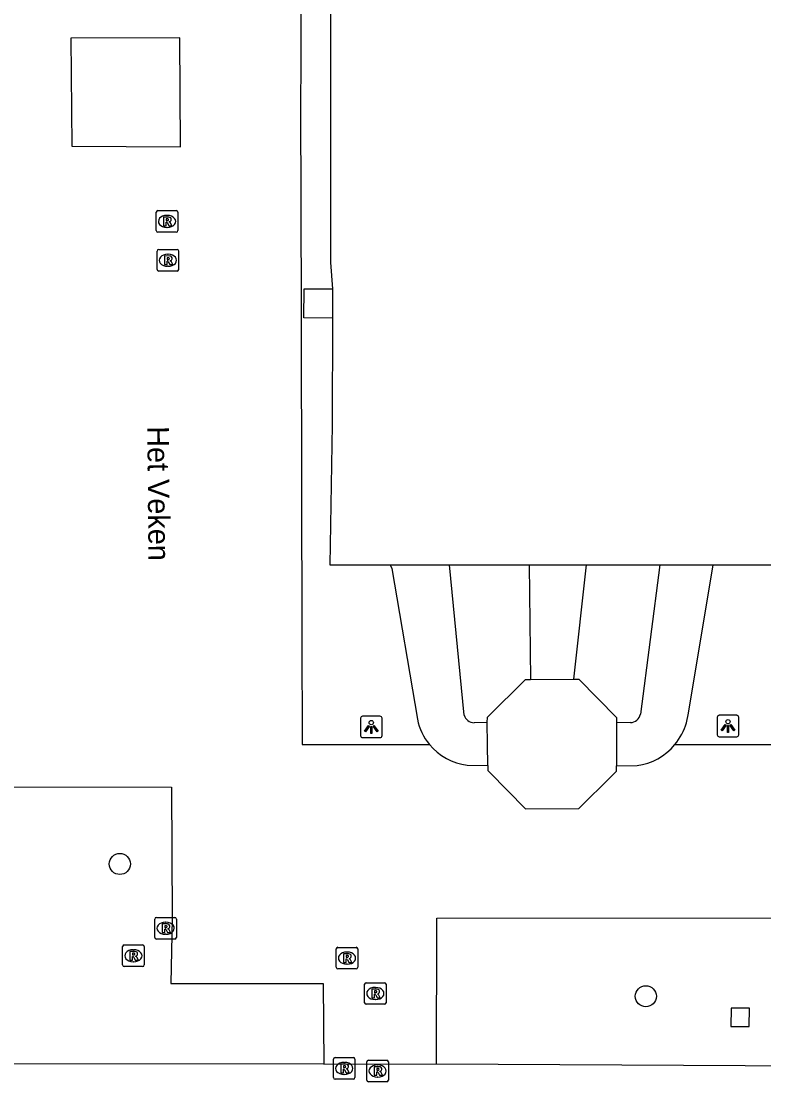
# Model space of a CAD drawing. Extents: x 161477 to 163040, y 383680 to 384868.
# Drawn here: x 162022.66 to 162057.1, y 384190.13 to 384239.31 of the extents above; entities that cross this region are included whole.
import ezdxf

# ---------------------------------------------------------------- set-up
doc = ezdxf.new("R2010")
doc.units = 0
for name, color, linetype in [('IMGEO_Boom', 7, 'Continuous'), ('IMGEO_Groenvoorziening', 7, 'Continuous'), ('IMGEO_Lichtpunt', 7, 'Continuous'), ('IMGEO_Openbare_ruimte_label', 7, 'Continuous'), ('IMGEO_Pand', 7, 'Continuous'), ('IMGEO_Rioolput', 7, 'Continuous'), ('IMGEO_Voetpad_gesloten', 7, 'Continuous'), ('IMGEO_Voetpad_open', 7, 'Continuous')]:
    doc.layers.add(name, color=color, linetype=linetype)

msp = doc.modelspace()

# ---------------------------------------------------------------- linework, layer by layer
at = {"layer": 'IMGEO_Boom'}
for centre in [(162027.23, 384200.233), (162051.624, 384194.101)]:
    msp.add_circle(centre, 0.489, dxfattribs=at)
at = {"layer": 'IMGEO_Groenvoorziening'}
for points in [[(162039.764, 384214.102), (162039.843, 384213.943), (162041.029, 384206.942)], [(162043.196, 384207.129), (162042.524, 384214.109)], [(162046.212, 384214.11), (162046.269, 384208.792)], [(162048.861, 384214.111), (162048.271, 384208.804)], [(162052.282, 384214.112), (162051.378, 384207.188)], [(162053.515, 384206.785), (162053.604, 384207.234), (162054.752, 384214.113)], [(162044.274, 384206.789), (162043.657, 384206.781)], [(162050.909, 384206.788), (162050.259, 384206.785)]]:
    msp.add_lwpolyline(points, dxfattribs=at)
for centre, radius, start, end in [((162043.669, 384207.49), 2.696, 191.7325, 219.4536), ((162043.678, 384207.288), 0.507, 198.2253, 267.6778), ((162050.877, 384207.3), 0.513, 273.5225, 347.3978), ((162050.885, 384207.55), 2.738, 319.4429, 343.7876)]:
    msp.add_arc(centre, radius, start, end, dxfattribs=at)
at = {"layer": 'IMGEO_Lichtpunt'}
for p, q in [((162038.393, 384206.993), (162038.393, 384206.186)), ((162038.393, 384206.993), (162038.393, 384206.186)), ((162039.295, 384207.088), (162038.487, 384207.088)), ((162039.295, 384207.088), (162038.487, 384207.088)), ((162039.389, 384206.186), (162039.389, 384206.993)), ((162039.389, 384206.186), (162039.389, 384206.993)), ((162054.938, 384207.032), (162054.938, 384206.225)), ((162054.938, 384207.032), (162054.938, 384206.225)), ((162055.84, 384207.127), (162055.032, 384207.127)), ((162055.84, 384207.127), (162055.032, 384207.127)), ((162055.934, 384206.225), (162055.934, 384207.032)), ((162055.934, 384206.225), (162055.934, 384207.032)), ((162038.487, 384206.092), (162039.295, 384206.092)), ((162038.487, 384206.092), (162039.295, 384206.092)), ((162055.032, 384206.131), (162055.84, 384206.131)), ((162055.032, 384206.131), (162055.84, 384206.131))]:
    msp.add_line(p, q, dxfattribs=at)
for points in [[(162038.767, 384206.657), (162038.806, 384206.629), (162038.618, 384206.367), (162038.58, 384206.394), (162038.767, 384206.657)], [(162038.869, 384206.609), (162038.916, 384206.609), (162038.916, 384206.287), (162038.869, 384206.287), (162038.869, 384206.609)], [(162038.979, 384206.629), (162039.017, 384206.656), (162039.204, 384206.394), (162039.165, 384206.366), (162038.979, 384206.629)], [(162055.312, 384206.696), (162055.351, 384206.668), (162055.163, 384206.406), (162055.125, 384206.433), (162055.312, 384206.696)], [(162055.414, 384206.648), (162055.461, 384206.648), (162055.461, 384206.326), (162055.414, 384206.326), (162055.414, 384206.648)], [(162055.524, 384206.668), (162055.562, 384206.695), (162055.749, 384206.433), (162055.71, 384206.405), (162055.524, 384206.668)]]:
    msp.add_lwpolyline(points, dxfattribs=at)
for centre in [(162038.892, 384206.791), (162055.437, 384206.83)]:
    msp.add_circle(centre, 0.0994, dxfattribs=at)
for centre, start, end in [((162038.487, 384206.993), 90, 180), ((162038.487, 384206.993), 90, 180), ((162039.295, 384206.993), 0, 90), ((162039.295, 384206.993), 0, 90), ((162055.032, 384207.032), 90, 180), ((162055.032, 384207.032), 90, 180), ((162055.84, 384207.032), 0, 90), ((162055.84, 384207.032), 0, 90), ((162038.487, 384206.186), 180, 270), ((162038.487, 384206.186), 180, 270), ((162039.295, 384206.186), 270, 0), ((162039.295, 384206.186), 270, 360), ((162055.032, 384206.225), 180, 270), ((162055.032, 384206.225), 180, 270), ((162055.84, 384206.225), 270, 0), ((162055.84, 384206.225), 270, 360)]:
    msp.add_arc(centre, 0.0946, start, end, dxfattribs=at)
at = {"layer": 'IMGEO_Pand'}
for points in [[(162082.399, 384225.651), (162082.408, 384231.898), (162082.412, 384234.268), (162082.422, 384240.901), (162061.823, 384240.891), (162060.867, 384240.892), (162058.494, 384240.893), (162057.612, 384240.894), (162036.997, 384240.896), (162036.996, 384234.345), (162036.996, 384231.857), (162036.996, 384231.817), (162036.996, 384228.133), (162037.096, 384226.903)], [(162037.096, 384226.903), (162037.088, 384225.547)], [(162037.088, 384225.547), (162037.077, 384220.594), (162036.972, 384214.106), (162039.764, 384214.102)], [(162054.752, 384214.113), (162082.389, 384214.105), (162082.384, 384220.627), (162082.385, 384220.86)], [(162039.764, 384214.102), (162042.524, 384214.109)], [(162042.524, 384214.109), (162046.212, 384214.11)], [(162046.212, 384214.11), (162048.861, 384214.111)], [(162048.861, 384214.111), (162052.282, 384214.112)], [(162052.282, 384214.112), (162054.752, 384214.113)], [(162044.274, 384206.789), (162044.281, 384207.048), (162046.041, 384208.79), (162046.269, 384208.792)], [(162046.269, 384208.792), (162048.271, 384208.804)], [(162048.271, 384208.804), (162048.518, 384208.804), (162050.258, 384207.019), (162050.259, 384206.785)], [(162044.299, 384204.794), (162044.287, 384205.769), (162044.274, 384206.789)], [(162050.259, 384206.785), (162050.262, 384205.769), (162050.265, 384204.78)], [(162044.299, 384204.794), (162044.302, 384204.562), (162044.371, 384204.491), (162046.038, 384202.787), (162048.513, 384202.804), (162050.048, 384204.318), (162050.266, 384204.533), (162050.265, 384204.78)]]:
    msp.add_lwpolyline(points, dxfattribs=at)
at = {"layer": 'IMGEO_Rioolput'}
for p, q in [((162028.918, 384229.606), (162028.918, 384230.458)), ((162028.993, 384230.532), (162029.845, 384230.532)), ((162029.919, 384230.458), (162029.919, 384229.606)), ((162029.406, 384230.312), (162029.431, 384230.312)), ((162029.845, 384229.532), (162028.993, 384229.532)), ((162029.429, 384229.752), (162029.404, 384229.752)), ((162028.957, 384227.802), (162028.957, 384228.654)), ((162029.032, 384228.728), (162029.884, 384228.728)), ((162029.445, 384228.508), (162029.47, 384228.508)), ((162029.958, 384228.654), (162029.958, 384227.802)), ((162029.468, 384227.948), (162029.443, 384227.948)), ((162029.884, 384227.728), (162029.032, 384227.728)), ((162028.853, 384196.827), (162028.853, 384197.679)), ((162028.928, 384197.753), (162029.78, 384197.753)), ((162029.341, 384197.533), (162029.366, 384197.533)), ((162029.854, 384197.679), (162029.854, 384196.827)), ((162029.364, 384196.973), (162029.339, 384196.973)), ((162027.433, 384196.479), (162028.285, 384196.479)), ((162029.78, 384196.753), (162028.928, 384196.753)), ((162027.358, 384195.553), (162027.358, 384196.405)), ((162027.846, 384196.259), (162027.871, 384196.259)), ((162028.359, 384196.405), (162028.359, 384195.553)), ((162037.264, 384195.442), (162037.264, 384196.294)), ((162037.339, 384196.368), (162038.191, 384196.368)), ((162037.752, 384196.148), (162037.777, 384196.148)), ((162038.265, 384196.294), (162038.265, 384195.442)), ((162027.869, 384195.699), (162027.844, 384195.699)), ((162037.775, 384195.588), (162037.75, 384195.588)), ((162028.285, 384195.479), (162027.433, 384195.479)), ((162038.191, 384195.368), (162037.339, 384195.368)), ((162038.579, 384193.802), (162038.579, 384194.654)), ((162038.654, 384194.728), (162039.506, 384194.728)), ((162039.067, 384194.508), (162039.092, 384194.508)), ((162039.58, 384194.654), (162039.58, 384193.802)), ((162039.506, 384193.728), (162038.654, 384193.728)), ((162039.09, 384193.948), (162039.065, 384193.948)), ((162037.135, 384190.329), (162037.135, 384191.181)), ((162037.21, 384191.255), (162038.062, 384191.255)), ((162038.136, 384191.181), (162038.136, 384190.329)), ((162038.685, 384190.208), (162038.685, 384191.06)), ((162038.76, 384191.134), (162039.612, 384191.134)), ((162039.686, 384191.06), (162039.686, 384190.208)), ((162037.623, 384191.035), (162037.648, 384191.035)), ((162039.173, 384190.914), (162039.198, 384190.914)), ((162038.062, 384190.255), (162037.21, 384190.255)), ((162037.646, 384190.475), (162037.621, 384190.475)), ((162039.612, 384190.134), (162038.76, 384190.134)), ((162039.196, 384190.354), (162039.171, 384190.354))]:
    msp.add_line(p, q, dxfattribs=at)
for points in [[(162028.918, 384229.606), (162028.918, 384230.458)], [(162028.993, 384230.532), (162029.845, 384230.532)], [(162029.919, 384230.458), (162029.919, 384229.606)], [(162029.507, 384230.23), (162029.255, 384230.232), (162029.255, 384229.832)], [(162029.255, 384229.832), (162029.379, 384229.832), (162029.379, 384229.994), (162029.39, 384229.994)], [(162029.433, 384230.151), (162029.379, 384230.151), (162029.379, 384230.07)], [(162029.379, 384230.07), (162029.431, 384230.07)], [(162029.437, 384229.965), (162029.508, 384229.832), (162029.648, 384229.832), (162029.583, 384229.958)], [(162029.845, 384229.532), (162028.993, 384229.532)], [(162028.957, 384227.802), (162028.957, 384228.654)], [(162029.032, 384228.728), (162029.884, 384228.728)], [(162029.958, 384228.654), (162029.958, 384227.802)], [(162029.546, 384228.426), (162029.294, 384228.428), (162029.294, 384228.028)], [(162029.294, 384228.028), (162029.418, 384228.028), (162029.418, 384228.19), (162029.429, 384228.19)], [(162029.472, 384228.347), (162029.418, 384228.347), (162029.418, 384228.266)], [(162029.418, 384228.266), (162029.47, 384228.266)], [(162029.476, 384228.161), (162029.547, 384228.028), (162029.687, 384228.028), (162029.622, 384228.154)], [(162029.884, 384227.728), (162029.032, 384227.728)], [(162028.853, 384196.827), (162028.853, 384197.679)], [(162028.928, 384197.753), (162029.78, 384197.753)], [(162029.442, 384197.451), (162029.19, 384197.453), (162029.19, 384197.053)], [(162029.854, 384197.679), (162029.854, 384196.827)], [(162029.19, 384197.053), (162029.314, 384197.053), (162029.314, 384197.215), (162029.325, 384197.215)], [(162029.368, 384197.372), (162029.314, 384197.372), (162029.314, 384197.291)], [(162029.314, 384197.291), (162029.366, 384197.291)], [(162029.372, 384197.186), (162029.443, 384197.053), (162029.583, 384197.053), (162029.518, 384197.179)], [(162027.433, 384196.479), (162028.285, 384196.479)], [(162029.78, 384196.753), (162028.928, 384196.753)], [(162027.358, 384195.553), (162027.358, 384196.405)], [(162027.947, 384196.177), (162027.695, 384196.179), (162027.695, 384195.779)], [(162027.873, 384196.098), (162027.819, 384196.098), (162027.819, 384196.017)], [(162027.819, 384196.017), (162027.871, 384196.017)], [(162028.359, 384196.405), (162028.359, 384195.553)], [(162037.264, 384195.442), (162037.264, 384196.294)], [(162037.339, 384196.368), (162038.191, 384196.368)], [(162037.853, 384196.066), (162037.601, 384196.068), (162037.601, 384195.668)], [(162037.779, 384195.987), (162037.725, 384195.987), (162037.725, 384195.906)], [(162038.265, 384196.294), (162038.265, 384195.442)], [(162027.695, 384195.779), (162027.819, 384195.779), (162027.819, 384195.941), (162027.83, 384195.941)], [(162027.877, 384195.912), (162027.948, 384195.779), (162028.088, 384195.779), (162028.023, 384195.905)], [(162037.601, 384195.668), (162037.725, 384195.668), (162037.725, 384195.83), (162037.736, 384195.83)], [(162037.725, 384195.906), (162037.777, 384195.906)], [(162037.783, 384195.801), (162037.854, 384195.668), (162037.994, 384195.668), (162037.929, 384195.794)], [(162028.285, 384195.479), (162027.433, 384195.479)], [(162038.191, 384195.368), (162037.339, 384195.368)], [(162038.579, 384193.802), (162038.579, 384194.654)], [(162038.654, 384194.728), (162039.506, 384194.728)], [(162039.58, 384194.654), (162039.58, 384193.802)], [(162039.168, 384194.426), (162038.916, 384194.428), (162038.916, 384194.028)], [(162038.916, 384194.028), (162039.04, 384194.028), (162039.04, 384194.19), (162039.051, 384194.19)], [(162039.094, 384194.347), (162039.04, 384194.347), (162039.04, 384194.266)], [(162039.04, 384194.266), (162039.092, 384194.266)], [(162039.098, 384194.161), (162039.169, 384194.028), (162039.309, 384194.028), (162039.244, 384194.154)], [(162039.506, 384193.728), (162038.654, 384193.728)], [(162037.135, 384190.329), (162037.135, 384191.181)], [(162037.21, 384191.255), (162038.062, 384191.255)], [(162038.136, 384191.181), (162038.136, 384190.329)], [(162038.685, 384190.208), (162038.685, 384191.06)], [(162038.76, 384191.134), (162039.612, 384191.134)], [(162039.686, 384191.06), (162039.686, 384190.208)], [(162037.724, 384190.953), (162037.472, 384190.955), (162037.472, 384190.555)], [(162037.472, 384190.555), (162037.596, 384190.555), (162037.596, 384190.717), (162037.607, 384190.717)], [(162037.65, 384190.874), (162037.596, 384190.874), (162037.596, 384190.793)], [(162037.596, 384190.793), (162037.648, 384190.793)], [(162037.654, 384190.688), (162037.725, 384190.555), (162037.865, 384190.555), (162037.8, 384190.681)], [(162039.274, 384190.832), (162039.022, 384190.834), (162039.022, 384190.434)], [(162039.022, 384190.434), (162039.146, 384190.434), (162039.146, 384190.596), (162039.157, 384190.596)], [(162039.2, 384190.753), (162039.146, 384190.753), (162039.146, 384190.672)], [(162039.146, 384190.672), (162039.198, 384190.672)], [(162039.204, 384190.567), (162039.275, 384190.434), (162039.415, 384190.434), (162039.35, 384190.56)], [(162038.062, 384190.255), (162037.21, 384190.255)], [(162039.612, 384190.134), (162038.76, 384190.134)]]:
    msp.add_lwpolyline(points, dxfattribs=at)
for centre, radius, start, end in [((162028.995, 384230.456), 0.0765, 91.552, 178.448), ((162028.995, 384230.456), 0.0765, 91.552, 178.448), ((162029.843, 384230.456), 0.0765, 1.552, 88.448), ((162029.843, 384230.456), 0.0765, 1.552, 88.448), ((162029.389, 384229.941), 0.0533, 26.0293, 88.6989), ((162029.415, 384230.259), 0.19, 274.7715, 282.9687), ((162029.439, 384230.055), 0.0964, 77.0061, 93.1865), ((162029.453, 384230.112), 0.0378, 276.6634, 79.6772), ((162029.506, 384230.12), 0.109, 350.3612, 89.416), ((162029.504, 384230.12), 0.112, 277.5842, 350.9817), ((162029.488, 384229.905), 0.108, 29.5134, 73.7905), ((162028.995, 384229.608), 0.0765, 181.552, 268.448), ((162028.995, 384229.608), 0.0765, 181.552, 268.448), ((162029.843, 384229.608), 0.0765, 271.552, 358.448), ((162029.843, 384229.608), 0.0765, 271.552, 358.448), ((162029.034, 384228.652), 0.0765, 91.552, 178.448), ((162029.034, 384228.652), 0.0765, 91.552, 178.448), ((162029.882, 384228.652), 0.0765, 1.552, 88.448), ((162029.882, 384228.652), 0.0765, 1.552, 88.448), ((162029.428, 384228.137), 0.0533, 26.0293, 88.6989), ((162029.454, 384228.455), 0.19, 274.7715, 282.9687), ((162029.478, 384228.251), 0.0964, 77.0061, 93.1865), ((162029.492, 384228.308), 0.0378, 276.6634, 79.6772), ((162029.545, 384228.316), 0.109, 350.3612, 89.416), ((162029.543, 384228.316), 0.112, 277.5842, 350.9817), ((162029.527, 384228.101), 0.108, 29.5134, 73.7905), ((162029.034, 384227.804), 0.0765, 181.552, 268.448), ((162029.034, 384227.804), 0.0765, 181.552, 268.448), ((162029.882, 384227.804), 0.0765, 271.552, 358.448), ((162029.882, 384227.804), 0.0765, 271.552, 358.448), ((162028.93, 384197.677), 0.0765, 91.552, 178.448), ((162028.93, 384197.677), 0.0765, 91.552, 178.448), ((162029.441, 384197.341), 0.109, 350.3612, 89.416), ((162029.778, 384197.677), 0.0765, 1.552, 88.448), ((162029.778, 384197.677), 0.0765, 1.552, 88.448), ((162029.324, 384197.162), 0.0533, 26.0293, 88.6989), ((162029.35, 384197.48), 0.19, 274.7715, 282.9687), ((162029.374, 384197.276), 0.0964, 77.0061, 93.1865), ((162029.388, 384197.333), 0.0378, 276.6634, 79.6772), ((162029.439, 384197.341), 0.112, 277.5842, 350.9817), ((162029.423, 384197.126), 0.108, 29.5134, 73.7905), ((162027.435, 384196.403), 0.0765, 91.552, 178.448), ((162027.435, 384196.403), 0.0765, 91.552, 178.448), ((162028.283, 384196.403), 0.0765, 1.552, 88.448), ((162028.283, 384196.403), 0.0765, 1.552, 88.448), ((162028.93, 384196.829), 0.0765, 181.552, 268.448), ((162028.93, 384196.829), 0.0765, 181.552, 268.448), ((162029.778, 384196.829), 0.0765, 271.552, 358.448), ((162029.778, 384196.829), 0.0765, 271.552, 358.448), ((162027.855, 384196.206), 0.19, 274.7715, 282.9687), ((162027.879, 384196.002), 0.0964, 77.0061, 93.1865), ((162027.893, 384196.059), 0.0378, 276.6634, 79.6772), ((162027.946, 384196.067), 0.109, 350.3612, 89.416), ((162027.944, 384196.067), 0.112, 277.5842, 350.9817), ((162037.341, 384196.292), 0.0765, 91.552, 178.448), ((162037.341, 384196.292), 0.0765, 91.552, 178.448), ((162037.785, 384195.891), 0.0964, 77.0061, 93.1865), ((162037.799, 384195.948), 0.0378, 276.6634, 79.6772), ((162037.852, 384195.956), 0.109, 350.3612, 89.416), ((162038.189, 384196.292), 0.0765, 1.552, 88.448), ((162038.189, 384196.292), 0.0765, 1.552, 88.448), ((162027.435, 384195.555), 0.0765, 181.552, 268.448), ((162027.435, 384195.555), 0.0765, 181.552, 268.448), ((162027.829, 384195.888), 0.0533, 26.0293, 88.6989), ((162027.928, 384195.852), 0.108, 29.5134, 73.7905), ((162028.283, 384195.555), 0.0765, 271.552, 358.448), ((162028.283, 384195.555), 0.0765, 271.552, 358.448), ((162037.735, 384195.777), 0.0533, 26.0293, 88.6989), ((162037.761, 384196.095), 0.19, 274.7715, 282.9687), ((162037.85, 384195.956), 0.112, 277.5842, 350.9817), ((162037.834, 384195.741), 0.108, 29.5134, 73.7905), ((162037.341, 384195.444), 0.0765, 181.552, 268.448), ((162037.341, 384195.444), 0.0765, 181.552, 268.448), ((162038.189, 384195.444), 0.0765, 271.552, 358.448), ((162038.189, 384195.444), 0.0765, 271.552, 358.448), ((162038.656, 384194.652), 0.0765, 91.552, 178.448), ((162038.656, 384194.652), 0.0765, 91.552, 178.448), ((162039.504, 384194.652), 0.0765, 1.552, 88.448), ((162039.504, 384194.652), 0.0765, 1.552, 88.448), ((162039.05, 384194.137), 0.0533, 26.0293, 88.6989), ((162039.076, 384194.455), 0.19, 274.7715, 282.9687), ((162039.1, 384194.251), 0.0964, 77.0061, 93.1865), ((162039.114, 384194.308), 0.0378, 276.6634, 79.6772), ((162039.167, 384194.316), 0.109, 350.3612, 89.416), ((162039.165, 384194.316), 0.112, 277.5842, 350.9817), ((162039.149, 384194.101), 0.108, 29.5134, 73.7905), ((162038.656, 384193.804), 0.0765, 181.552, 268.448), ((162038.656, 384193.804), 0.0765, 181.552, 268.448), ((162039.504, 384193.804), 0.0765, 271.552, 358.448), ((162039.504, 384193.804), 0.0765, 271.552, 358.448), ((162037.212, 384191.179), 0.0765, 91.552, 178.448), ((162037.212, 384191.179), 0.0765, 91.552, 178.448), ((162038.06, 384191.179), 0.0765, 1.552, 88.448), ((162038.06, 384191.179), 0.0765, 1.552, 88.448), ((162038.762, 384191.058), 0.0765, 91.552, 178.448), ((162038.762, 384191.058), 0.0765, 91.552, 178.448), ((162039.61, 384191.058), 0.0765, 1.552, 88.448), ((162039.61, 384191.058), 0.0765, 1.552, 88.448), ((162037.606, 384190.664), 0.0533, 26.0293, 88.6989), ((162037.632, 384190.982), 0.19, 274.7715, 282.9687), ((162037.656, 384190.778), 0.0964, 77.0061, 93.1865), ((162037.67, 384190.835), 0.0378, 276.6634, 79.6772), ((162037.723, 384190.843), 0.109, 350.3612, 89.416), ((162037.721, 384190.843), 0.112, 277.5842, 350.9817), ((162037.705, 384190.628), 0.108, 29.5134, 73.7905), ((162039.156, 384190.543), 0.0533, 26.0293, 88.6989), ((162039.182, 384190.861), 0.19, 274.7715, 282.9687), ((162039.206, 384190.657), 0.0964, 77.0061, 93.1865), ((162039.22, 384190.714), 0.0378, 276.6634, 79.6772), ((162039.273, 384190.722), 0.109, 350.3612, 89.416), ((162039.271, 384190.722), 0.112, 277.5842, 350.9817), ((162039.255, 384190.507), 0.108, 29.5134, 73.7905), ((162037.212, 384190.331), 0.0765, 181.552, 268.448), ((162037.212, 384190.331), 0.0765, 181.552, 268.448), ((162038.06, 384190.331), 0.0765, 271.552, 358.448), ((162038.06, 384190.331), 0.0765, 271.552, 358.448), ((162038.762, 384190.21), 0.0765, 181.552, 268.448), ((162038.762, 384190.21), 0.0765, 181.552, 268.448), ((162039.61, 384190.21), 0.0765, 271.552, 358.448), ((162039.61, 384190.21), 0.0765, 271.552, 358.448)]:
    msp.add_arc(centre, radius, start, end, dxfattribs=at)
for centre, major_axis, ratio, start_param, end_param in [((162029.405, 384230.032), (-0.387, 0.002), 0.722429, 4.712389, 7.853982), ((162029.43, 384230.032), (-0.39, 0.002), 0.717154, 1.570796, 4.712389), ((162029.444, 384228.228), (-0.387, 0.002), 0.722429, 4.712389, 7.853982), ((162029.469, 384228.228), (-0.39, 0.002), 0.717154, 1.570796, 4.712389), ((162029.34, 384197.253), (-0.387, 0.002), 0.722429, 4.712389, 7.853982), ((162029.365, 384197.253), (-0.39, 0.002), 0.717154, 1.570796, 4.712389), ((162027.845, 384195.979), (-0.387, 0.002), 0.722429, 4.712389, 7.853982), ((162027.87, 384195.979), (-0.39, 0.002), 0.717154, 1.570796, 4.712389), ((162037.751, 384195.868), (-0.387, 0.002), 0.722429, 4.712389, 7.853982), ((162037.776, 384195.868), (-0.39, 0.002), 0.717154, 1.570796, 4.712389), ((162039.066, 384194.228), (-0.387, 0.002), 0.722429, 4.712389, 7.853982), ((162039.091, 384194.228), (-0.39, 0.002), 0.717154, 1.570796, 4.712389), ((162037.622, 384190.755), (-0.387, 0.002), 0.722429, 4.712389, 7.853982), ((162037.647, 384190.755), (-0.39, 0.002), 0.717154, 1.570796, 4.712389), ((162039.172, 384190.634), (-0.387, 0.002), 0.722429, 4.712389, 7.853982), ((162039.197, 384190.634), (-0.39, 0.002), 0.717154, 1.570796, 4.712389)]:
    msp.add_ellipse(centre, major_axis=major_axis, ratio=ratio, start_param=start_param, end_param=end_param, dxfattribs=at)
at = {"layer": 'IMGEO_Voetpad_gesloten'}
msp.add_lwpolyline([(162056.426, 384193.543), (162055.576, 384193.548), (162055.571, 384192.698), (162056.418, 384192.693), (162056.426, 384193.543)], dxfattribs=at)
at = {"layer": 'IMGEO_Voetpad_open'}
for points in [[(162088.744, 384225.652), (162088.671, 384242.578), (162079.599, 384242.59), (162035.635, 384242.572), (162035.61, 384234.345), (162035.617, 384231.857), (162035.674, 384210.817), (162035.689, 384205.774), (162036.977, 384205.775), (162039.977, 384205.776), (162041.587, 384205.777)], [(162030.015, 384238.541), (162024.951, 384238.53), (162025, 384233.524), (162030.043, 384233.492), (162030.015, 384238.541)], [(162041.924, 384190.961), (162041.937, 384197.345), (162041.938, 384197.717), (162098.373, 384197.75), (162098.374, 384205.812), (162106.811, 384205.822), (162106.921, 384228.996)], [(162037.088, 384225.547), (162035.768, 384225.554), (162035.776, 384226.904), (162037.096, 384226.903)], [(162052.966, 384205.769), (162063.039, 384205.769), (162063.039, 384203.191), (162088.916, 384203.191), (162088.916, 384210.562), (162088.75, 384220.868)], [(162043.346, 384204.815), (162044.299, 384204.794)], [(162050.265, 384204.78), (162051.223, 384204.798)], [(162021.995, 384203.805), (162022.138, 384203.805), (162029.625, 384203.8), (162029.664, 384197.71), (162029.597, 384194.691), (162036.663, 384194.685), (162036.69, 384190.945)], [(162036.69, 384190.945), (162021.037, 384190.964), (161965.965, 384191.055), (161965.985, 384199.331)], [(162036.69, 384190.945), (162041.924, 384190.961)], [(162041.924, 384190.961), (162056.233, 384190.888), (162080.169, 384190.88)]]:
    msp.add_lwpolyline(points, dxfattribs=at)
for centre, radius, start, end in [((162043.66, 384207.478), 2.682, 219.3749, 263.2764), ((162050.87, 384207.482), 2.707, 277.4979, 320.7452)]:
    msp.add_arc(centre, radius, start, end, dxfattribs=at)

# ---------------------------------------------------------------- texts
at = {"layer": 'IMGEO_Openbare_ruimte_label'}
msp.add_text('Het Veken', height=1, rotation=270.5156, dxfattribs=at).set_placement((162028.503, 384220.53))

doc.saveas('drawing.dxf')
